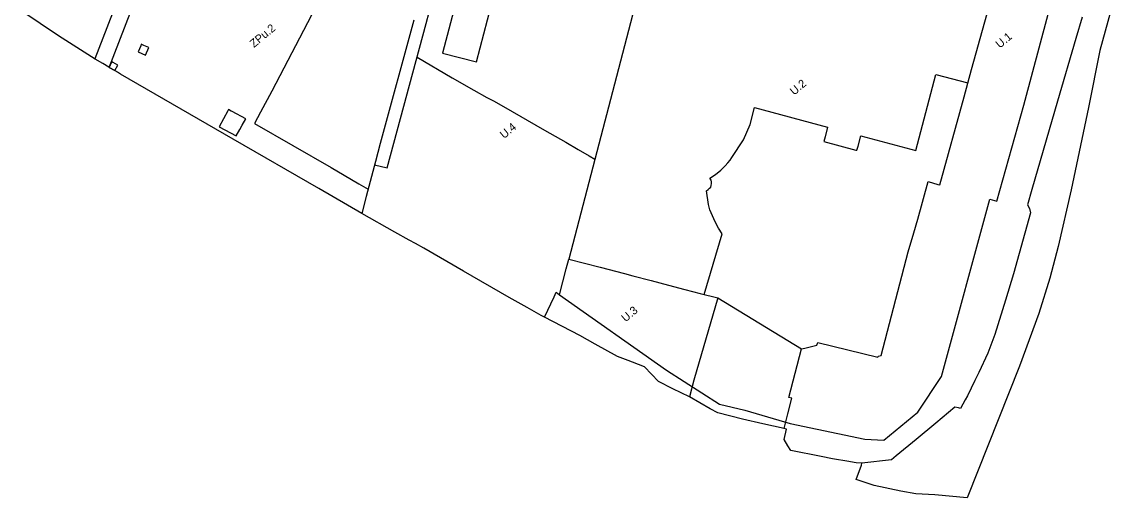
# Model space of a CAD drawing. Extents: x 7418616 to 7420822, y 5550745 to 5553106.
# Drawn here: x 7420107 to 7420784, y 5550745 to 5551038 of the extents above; entities that cross this region are included whole.
import ezdxf

# ---------------------------------------------------------------- set-up
doc = ezdxf.new("R2010")
doc.units = 0
for name, color, linetype in [('granica obszaru objętego planem', 7, 'Continuous'), ('granica strefy zwiększonej wysokości zabudowy', 7, 'Continuous'), ('linie rozgraniczające', 7, 'Continuous'), ('nieprzekraczalne linie lokalizacyjne', 7, 'Continuous'), ('nieprzekraczalne linie zabudowy', 7, 'Continuous'), ('obowiązujące linie zabudowy', 7, 'Continuous'), ('przeznaczenia terenów', 7, 'Continuous')]:
    doc.layers.add(name, color=color, linetype=linetype)

msp = doc.modelspace()

# ---------------------------------------------------------------- linework, layer by layer
at = {"layer": 'granica obszaru objętego planem'}
msp.add_lwpolyline([(7420783.83, 5551070.13), (7420770.23, 5551020.07), (7420763.2, 5550985), (7420752.51, 5550934.39), (7420744.6, 5550899.43), (7420739.39, 5550880), (7420732.76, 5550858.31), (7420720.87, 5550825.88), (7420688.59, 5550744.88), (7420668.75, 5550746.76), (7420657.04, 5550747.48), (7420647.78, 5550749.06), (7420631.33, 5550752.52), (7420620.28, 5550756.15), (7420623.6, 5550765.14), (7420623.79, 5550766.34), (7420620.37, 5550766.55), (7420616.75, 5550767.16), (7420615.81, 5550767.32), (7420605.84, 5550769.02), (7420598.69, 5550770.31), (7420580.15, 5550774.16), (7420578.38, 5550776.96), (7420575.94, 5550780.81), (7420577.48, 5550787.18), (7420576.06, 5550787.51), (7420562.99, 5550790.39), (7420550.42, 5550793.4), (7420535.28, 5550797.16), (7420530.58, 5550799.76), (7420517.75, 5550807.06), (7420507.61, 5550812.03), (7420498.8, 5550816.57), (7420490.16, 5550825.61), (7420482.78, 5550828.43), (7420480.05, 5550829.47), (7420473.57, 5550831.81), (7420459.73, 5550839.51), (7420450.32, 5550844.86), (7420428.64, 5550856.05), (7420426.63, 5550857.17), (7420417.9, 5550862.05), (7420406.96, 5550868.16), (7420378.85, 5550884.3), (7420354.35, 5550898.49), (7420349.27, 5550901.26), (7420345.28, 5550903.44), (7420336.51, 5550908.23), (7420316.17, 5550919.88), (7420289.9, 5550935.1), (7420237.21, 5550965.51), (7420167.9, 5551005.52), (7420165.92, 5551006.67), (7420160.58, 5551009.73), (7420156.87, 5551011.96), (7420152.28, 5551014.73), (7420129.73, 5551029.01), (7420107.22, 5551044.12)], dxfattribs=at)
at = {"layer": 'granica strefy zwiększonej wysokości zabudowy'}
msp.add_lwpolyline([(7420350.26, 5551015.85), (7420371.88, 5551003.14), (7420385.17, 5550995.6), (7420393.23, 5550991.2), (7420397.18, 5550989.04), (7420403.35, 5550985.67), (7420428.69, 5550971), (7420441.63, 5550963.57), (7420449.31, 5550959.16), (7420456.07, 5550955.28), (7420459.61, 5550953.3)], dxfattribs=at)
at = {"layer": 'linie rozgraniczające'}
for points in [[(7420416.4, 5551210.73), (7420391.25, 5551114.44), (7420387.03, 5551098.6), (7420375.73, 5551055.84), (7420365.88, 5551018.47), (7420386.78, 5551013.02), (7420393.53, 5551038.97), (7420401.62, 5551069.56)], [(7420194.32, 5551127.45), (7420193.34, 5551124.74), (7420167.72, 5551055.81), (7420151.93, 5551014.95)], [(7420576.06, 5550787.51), (7420578.37, 5550796.59), (7420580.84, 5550806.25), (7420578.99, 5550806.68), (7420586.68, 5550836.57), (7420588.69, 5550837.04), (7420596.17, 5550838.79), (7420596.67, 5550840.46), (7420633.7, 5550831.52), (7420633.88, 5550832.15), (7420635.69, 5550832.49), (7420652.27, 5550896.33), (7420655.83, 5550907.98), (7420658.29, 5550916.34), (7420664.52, 5550939.44), (7420670.58, 5550937.72), (7420671.79, 5550937.38), (7420686.67, 5550991.47), (7420691.29, 5551008.28), (7420706.19, 5551062.05), (7420712.87, 5551086.14), (7420724.45, 5551127.9)], [(7420160.8, 5551009.6), (7420177.25, 5551052.17), (7420202.83, 5551121)], [(7420783.83, 5551070.13), (7420770.23, 5551020.07), (7420763.2, 5550985), (7420752.51, 5550934.39), (7420744.6, 5550899.43), (7420739.39, 5550880), (7420732.76, 5550858.31), (7420720.87, 5550825.88), (7420688.59, 5550744.88), (7420668.75, 5550746.76), (7420657.04, 5550747.48), (7420647.78, 5550749.06), (7420631.33, 5550752.52), (7420620.28, 5550756.15), (7420623.6, 5550765.14), (7420623.79, 5550766.34), (7420620.37, 5550766.55), (7420616.75, 5550767.16), (7420615.81, 5550767.32), (7420605.84, 5550769.02), (7420598.69, 5550770.31), (7420580.15, 5550774.16), (7420578.38, 5550776.96), (7420575.94, 5550780.81), (7420577.48, 5550787.18), (7420576.06, 5550787.51), (7420562.99, 5550790.39), (7420550.42, 5550793.4), (7420535.28, 5550797.16), (7420530.58, 5550799.76), (7420517.75, 5550807.06), (7420507.61, 5550812.03), (7420498.8, 5550816.57), (7420490.16, 5550825.61), (7420482.78, 5550828.43), (7420480.05, 5550829.47), (7420473.57, 5550831.81), (7420459.73, 5550839.51), (7420450.32, 5550844.86), (7420428.64, 5550856.05), (7420426.63, 5550857.17), (7420417.9, 5550862.05), (7420406.96, 5550868.16), (7420378.85, 5550884.3), (7420354.35, 5550898.49), (7420349.27, 5550901.26), (7420345.28, 5550903.44), (7420336.51, 5550908.23), (7420316.17, 5550919.88), (7420289.9, 5550935.1), (7420237.21, 5550965.51), (7420167.9, 5551005.52), (7420165.92, 5551006.67), (7420160.58, 5551009.73), (7420156.87, 5551011.96), (7420152.28, 5551014.73), (7420129.73, 5551029.01), (7420107.22, 5551044.12)], [(7420401.62, 5551069.56), (7420411.19, 5551066.74), (7420421.57, 5551063.94), (7420432.94, 5551060.93), (7420442.75, 5551058.24), (7420453.49, 5551055.26), (7420463.38, 5551052.22), (7420483.93, 5551046.39), (7420448.44, 5550910.56), (7420443.54, 5550891.79)], [(7420348.19, 5551038.78), (7420327.59, 5550962.8), (7420324.67, 5550951.81), (7420318.94, 5550930.36), (7420316.17, 5550919.88)], [(7420759.25, 5551040.43), (7420755.39, 5551027.32), (7420744.09, 5550988.93), (7420728.38, 5550934.48), (7420725.69, 5550925.19), (7420726.89, 5550922.88), (7420727.53, 5550920.18), (7420717.02, 5550882.79), (7420712.19, 5550866.6), (7420705.66, 5550845.4), (7420701.31, 5550833.96), (7420695.72, 5550822.07), (7420693.34, 5550817.21), (7420688.84, 5550807.68), (7420687.34, 5550805.28), (7420684.45, 5550799.94), (7420683.27, 5550800.22), (7420681.1, 5550800.73), (7420669.24, 5550790.88), (7420657.13, 5550780.83), (7420644.97, 5550770.73), (7420642.01, 5550768.26), (7420623.79, 5550766.34)], [(7420428.64, 5550856.05), (7420434.58, 5550868.65), (7420435.85, 5550871.34), (7420437.81, 5550869.75), (7420441.98, 5550885.79), (7420443.54, 5550891.79)], [(7420443.54, 5550891.79), (7420462.83, 5550886.74), (7420477.8, 5550882.82), (7420482.95, 5550881.48), (7420494.24, 5550878.53), (7420504.85, 5550875.74), (7420515.02, 5550873.08), (7420524.29, 5550870.66), (7420535.28, 5550867.94), (7420520.56, 5550817.31), (7420517.75, 5550807.06)]]:
    msp.add_lwpolyline(points, dxfattribs=at)
at = {"layer": 'nieprzekraczalne linie lokalizacyjne'}
msp.add_lwpolyline([(7420297.83, 5551067.7), (7420295.49, 5551062.73), (7420289.38, 5551049.77), (7420289.25, 5551049.5), (7420288.98, 5551048.92), (7420288.08, 5551047.01), (7420287.98, 5551046.8), (7420287.83, 5551046.48), (7420260.94, 5550994.94), (7420254.02, 5550982.09), (7420250.32, 5550975.22), (7420297.33, 5550948), (7420305.3, 5550943.4), (7420314.47, 5550938.1), (7420320.13, 5550934.82)], dxfattribs=at)
at = {"layer": 'nieprzekraczalne linie zabudowy'}
for points in [[(7420324.13, 5550949.79), (7420331.82, 5550947.8), (7420355.92, 5551036.71), (7420379.85, 5551127.4), (7420388.72, 5551161.46), (7420402.49, 5551214.53)], [(7420437.81, 5550869.75), (7420503.75, 5550823.55), (7420536.23, 5550802.55), (7420551.82, 5550798.79), (7420579.62, 5550790.61), (7420625.69, 5550781.05), (7420637.4, 5550780.39), (7420658.17, 5550797.57), (7420672.86, 5550819.48), (7420702.52, 5550928.61), (7420706.94, 5550927.47), (7420723.51, 5550986.46), (7420752.47, 5551095.47)], [(7420526.87, 5550870.02), (7420537.85, 5550907.4), (7420535.69, 5550910.8), (7420533.58, 5550914.74), (7420530.37, 5550922.04), (7420529.45, 5550925.3), (7420528.21, 5550933.79), (7420529.34, 5550934.49), (7420530.15, 5550935.29), (7420530.84, 5550936), (7420531.18, 5550936.93), (7420531.42, 5550938.15), (7420531.28, 5550939.22), (7420531.05, 5550940.27), (7420530.76, 5550941), (7420530.39, 5550941.46), (7420533.88, 5550943.8), (7420537, 5550946.49), (7420539.73, 5550949.15), (7420541.44, 5550951.04), (7420542.72, 5550952.59), (7420543.88, 5550954.2), (7420551.09, 5550965.08), (7420555.15, 5550974.5), (7420557.76, 5550984.98), (7420602.77, 5550972.91), (7420601.16, 5550966.9), (7420600.38, 5550964.12), (7420620.05, 5550958.84), (7420620.74, 5550958.66), (7420621.45, 5550961.19), (7420623.17, 5550967.64), (7420657.05, 5550958.64), (7420669.38, 5551005.2), (7420689.06, 5551000.2)], [(7420535.28, 5550867.94), (7420586.68, 5550836.57)]]:
    msp.add_lwpolyline(points, dxfattribs=at)
at = {"layer": 'obowiązujące linie zabudowy'}
for points in [[(7420180.6, 5551023.84), (7420180.23, 5551022.99), (7420178.62, 5551019.25), (7420183.25, 5551017.23), (7420185.16, 5551021.88), (7420182.23, 5551023.14), (7420181.82, 5551023.31), (7420180.6, 5551023.84)], [(7420162.52, 5551013.13), (7420162.16, 5551012.49), (7420161.38, 5551011.09), (7420160.63, 5551009.76), (7420160.82, 5551009.65), (7420164.23, 5551007.75), (7420166.15, 5551011.08), (7420163.28, 5551012.7), (7420163.07, 5551012.82), (7420162.52, 5551013.13)], [(7420234.29, 5550983.66), (7420233.85, 5550982.85), (7420228.55, 5550973.08), (7420238.96, 5550967.47), (7420241.12, 5550971.36), (7420242.62, 5550974.05), (7420244.8, 5550977.97), (7420236.46, 5550982.49), (7420235.85, 5550982.82), (7420234.29, 5550983.66)]]:
    msp.add_lwpolyline(points, dxfattribs=at)

# ---------------------------------------------------------------- texts
at = {"layer": 'przeznaczenia terenów'}
for s, p in [('ZPu.2', (7420249.9, 5551021.52)), ('U.1', (7420708.65, 5551021.14)), ('U.2', (7420582.12, 5550992.24)), ('U.4', (7420403.75, 5550965.52)), ('U.3', (7420478.46, 5550852.8))]:
    msp.add_text(s, height=5, rotation=39.84394, dxfattribs=at).set_placement(p)

doc.saveas('drawing.dxf')
